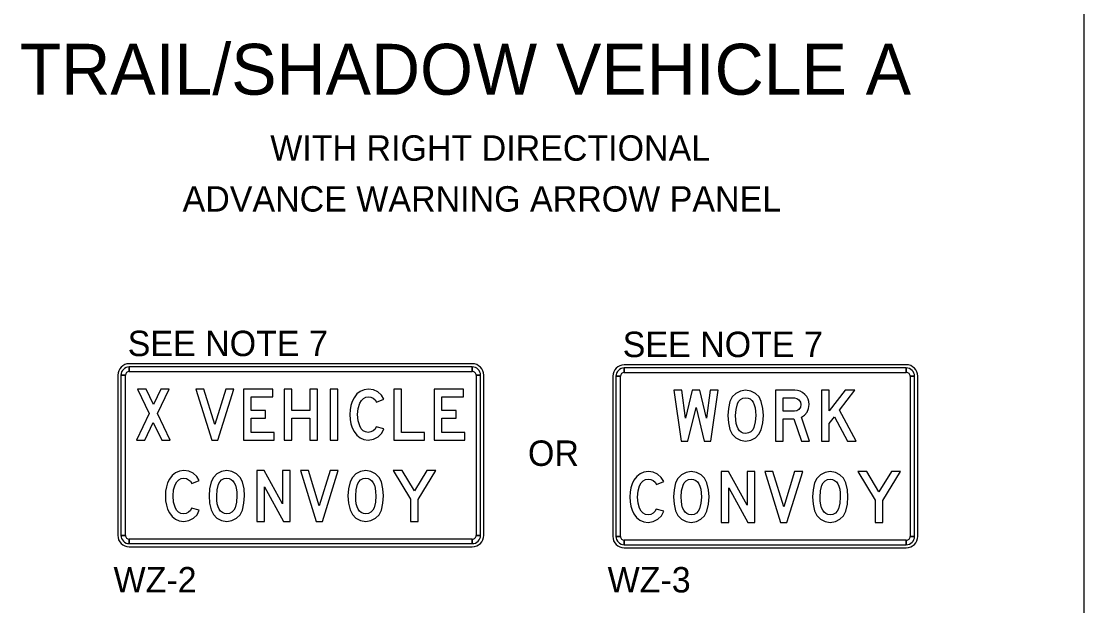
# Model space of a CAD drawing. Extents: x 1374027 to 1374537, y 380415 to 381405.
# Drawn here: x 1374116.23 to 1374141.31, y 381365.09 to 381378.88 of the extents above; entities that cross this region are included whole.
import ezdxf

# ---------------------------------------------------------------- set-up
doc = ezdxf.new("R2010")
doc.units = 0
doc.layers.add('Working Level 1', color=7, linetype='Continuous')

msp = doc.modelspace()

# ---------------------------------------------------------------- linework, layer by layer
at = {"layer": 'Working Level 1'}
for p, q in [((1374141.313, 381402.674), (1374141.313, 381297.674)), ((1374126.877, 381370.796), (1374118.777, 381370.796)), ((1374118.777, 381370.616), (1374118.777, 381370.721)), ((1374126.877, 381370.721), (1374126.877, 381370.616)), ((1374137.124, 381370.772), (1374130.464, 381370.772)), ((1374118.507, 381370.526), (1374118.507, 381366.746)), ((1374118.582, 381370.526), (1374118.687, 381370.526)), ((1374126.967, 381370.526), (1374127.072, 381370.526)), ((1374127.147, 381366.746), (1374127.147, 381370.526)), ((1374130.194, 381370.502), (1374130.194, 381366.722)), ((1374130.269, 381370.502), (1374130.374, 381370.502)), ((1374130.464, 381370.592), (1374130.464, 381370.697)), ((1374137.124, 381370.697), (1374137.124, 381370.592)), ((1374137.214, 381370.502), (1374137.319, 381370.502)), ((1374137.394, 381366.722), (1374137.394, 381370.502)), ((1374118.687, 381366.746), (1374118.582, 381366.746)), ((1374127.072, 381366.746), (1374126.967, 381366.746)), ((1374130.374, 381366.722), (1374130.269, 381366.722)), ((1374137.319, 381366.722), (1374137.214, 381366.722)), ((1374118.777, 381366.551), (1374118.777, 381366.656)), ((1374118.777, 381366.476), (1374126.877, 381366.476)), ((1374126.877, 381366.656), (1374126.877, 381366.551)), ((1374130.464, 381366.527), (1374130.464, 381366.632)), ((1374130.464, 381366.452), (1374137.124, 381366.452)), ((1374137.124, 381366.632), (1374137.124, 381366.527))]:
    msp.add_line(p, q, dxfattribs=at)
for points in [[(1374126.877, 381370.721), (1374118.777, 381370.721), (1374118.777, 381370.616), (1374126.877, 381370.616), (1374126.877, 381370.721)], [(1374118.582, 381370.526), (1374118.582, 381366.746), (1374118.687, 381366.746), (1374118.687, 381370.526), (1374118.582, 381370.526)], [(1374127.072, 381366.746), (1374127.072, 381370.526), (1374126.967, 381370.526), (1374126.967, 381366.746), (1374127.072, 381366.746)], [(1374130.269, 381370.502), (1374130.269, 381366.722), (1374130.374, 381366.722), (1374130.374, 381370.502), (1374130.269, 381370.502)], [(1374137.124, 381370.697), (1374130.464, 381370.697), (1374130.464, 381370.592), (1374137.124, 381370.592), (1374137.124, 381370.697)], [(1374137.319, 381366.722), (1374137.319, 381370.502), (1374137.214, 381370.502), (1374137.214, 381366.722), (1374137.319, 381366.722)], [(1374119.746, 381368.996), (1374119.448, 381369.624), (1374119.722, 381370.196), (1374119.521, 381370.196), (1374119.347, 381369.833), (1374119.174, 381370.196), (1374118.973, 381370.196), (1374119.247, 381369.623), (1374118.946, 381368.996), (1374119.146, 381368.996), (1374119.346, 381369.413), (1374119.546, 381368.996)], [(1374121.245, 381370.196), (1374121.056, 381370.196), (1374120.798, 381369.366), (1374120.541, 381370.196), (1374120.352, 381370.196), (1374120.724, 381368.996), (1374120.873, 381368.996)], [(1374122.202, 381369.177), (1374121.658, 381369.177), (1374121.658, 381369.516), (1374121.998, 381369.516), (1374121.998, 381369.697), (1374121.658, 381369.697), (1374121.658, 381370.014), (1374122.166, 381370.014), (1374122.166, 381370.196), (1374121.477, 381370.196), (1374121.477, 381368.996), (1374122.202, 381368.996)], [(1374123.225, 381368.996), (1374123.225, 381370.196), (1374123.044, 381370.196), (1374123.044, 381369.697), (1374122.614, 381369.697), (1374122.614, 381370.196), (1374122.433, 381370.196), (1374122.433, 381368.996), (1374122.614, 381368.996), (1374122.614, 381369.516), (1374123.044, 381369.516), (1374123.044, 381368.996)], [(1374123.702, 381368.996), (1374123.702, 381370.196), (1374123.521, 381370.196), (1374123.521, 381368.996)], [(1374124.79, 381369.262), (1374124.609, 381369.308), (1374124.582, 381369.255), (1374124.538, 381369.214), (1374124.482, 381369.186), (1374124.419, 381369.177), (1374124.356, 381369.186), (1374124.302, 381369.215), (1374124.256, 381369.263), (1374124.22, 381369.33), (1374124.182, 381369.453), (1374124.17, 381369.596), (1374124.183, 381369.739), (1374124.221, 381369.863), (1374124.259, 381369.929), (1374124.306, 381369.976), (1374124.361, 381370.005), (1374124.425, 381370.014), (1374124.485, 381370.006), (1374124.54, 381369.981), (1374124.585, 381369.942), (1374124.616, 381369.892), (1374124.79, 381369.96), (1374124.731, 381370.056), (1374124.646, 381370.131), (1374124.542, 381370.179), (1374124.428, 381370.196), (1374124.322, 381370.183), (1374124.23, 381370.145), (1374124.151, 381370.083), (1374124.086, 381369.995), (1374124.043, 381369.909), (1374124.013, 381369.814), (1374123.995, 381369.709), (1374123.989, 381369.596), (1374123.995, 381369.483), (1374124.013, 381369.379), (1374124.043, 381369.284), (1374124.085, 381369.198), (1374124.149, 381369.109), (1374124.227, 381369.046), (1374124.318, 381369.008), (1374124.422, 381368.996), (1374124.544, 381369.014), (1374124.654, 381369.07), (1374124.739, 381369.155)], [(1374125.746, 381368.996), (1374125.746, 381369.177), (1374125.202, 381369.177), (1374125.202, 381370.196), (1374125.021, 381370.196), (1374125.021, 381368.996)], [(1374126.702, 381369.177), (1374126.158, 381369.177), (1374126.158, 381369.516), (1374126.498, 381369.516), (1374126.498, 381369.697), (1374126.158, 381369.697), (1374126.158, 381370.014), (1374126.666, 381370.014), (1374126.666, 381370.196), (1374125.977, 381370.196), (1374125.977, 381368.996), (1374126.702, 381368.996)], [(1374132.68, 381370.172), (1374132.497, 381370.172), (1374132.405, 381369.515), (1374132.246, 381370.172), (1374132.071, 381370.172), (1374131.913, 381369.514), (1374131.821, 381370.172), (1374131.637, 381370.172), (1374131.805, 381368.972), (1374131.969, 381368.972), (1374132.159, 381369.762), (1374132.349, 381368.972), (1374132.512, 381368.972)], [(1374133.75, 381369.573), (1374133.738, 381369.744), (1374133.701, 381369.904), (1374133.647, 381370.013), (1374133.561, 381370.098), (1374133.452, 381370.153), (1374133.33, 381370.172), (1374133.208, 381370.153), (1374133.1, 381370.098), (1374133.015, 381370.012), (1374132.961, 381369.903), (1374132.924, 381369.743), (1374132.912, 381369.573), (1374132.924, 381369.403), (1374132.961, 381369.242), (1374133.015, 381369.133), (1374133.1, 381369.047), (1374133.208, 381368.991), (1374133.33, 381368.972), (1374133.452, 381368.991), (1374133.56, 381369.046), (1374133.646, 381369.131), (1374133.7, 381369.24), (1374133.737, 381369.401)], [(1374133.569, 381369.572), (1374133.558, 381369.426), (1374133.526, 381369.291), (1374133.497, 381369.234), (1374133.452, 381369.191), (1374133.396, 381369.163), (1374133.332, 381369.153), (1374133.276, 381369.16), (1374133.227, 381369.18), (1374133.186, 381369.212), (1374133.153, 381369.258), (1374133.127, 381369.317), (1374133.108, 381369.389), (1374133.097, 381369.474), (1374133.093, 381369.572), (1374133.104, 381369.717), (1374133.136, 381369.852), (1374133.164, 381369.909), (1374133.209, 381369.953), (1374133.266, 381369.982), (1374133.332, 381369.991), (1374133.387, 381369.984), (1374133.435, 381369.965), (1374133.476, 381369.932), (1374133.509, 381369.886), (1374133.535, 381369.827), (1374133.554, 381369.756), (1374133.565, 381369.67)], [(1374134.838, 381368.972), (1374134.649, 381369.533), (1374134.723, 381369.585), (1374134.78, 381369.657), (1374134.817, 381369.742), (1374134.83, 381369.835), (1374134.823, 381369.902), (1374134.805, 381369.964), (1374134.773, 381370.021), (1374134.73, 381370.073), (1374134.677, 381370.116), (1374134.62, 381370.147), (1374134.557, 381370.166), (1374134.49, 381370.172), (1374134.037, 381370.172), (1374134.037, 381368.972), (1374134.218, 381368.972), (1374134.218, 381369.493), (1374134.47, 381369.493), (1374134.647, 381368.972)], [(1374134.218, 381369.674), (1374134.218, 381369.991), (1374134.482, 381369.991), (1374134.54, 381369.979), (1374134.589, 381369.944), (1374134.622, 381369.893), (1374134.633, 381369.833), (1374134.622, 381369.771), (1374134.589, 381369.72), (1374134.54, 381369.685), (1374134.482, 381369.674)], [(1374135.938, 381368.972), (1374135.548, 381369.703), (1374135.909, 381370.172), (1374135.68, 381370.172), (1374135.306, 381369.686), (1374135.306, 381370.172), (1374135.125, 381370.172), (1374135.125, 381368.972), (1374135.306, 381368.972), (1374135.306, 381369.389), (1374135.427, 381369.546), (1374135.733, 381368.972)], [(1374120.431, 381367.342), (1374120.249, 381367.388), (1374120.223, 381367.335), (1374120.179, 381367.294), (1374120.122, 381367.266), (1374120.06, 381367.257), (1374119.997, 381367.266), (1374119.943, 381367.295), (1374119.897, 381367.343), (1374119.86, 381367.41), (1374119.823, 381367.533), (1374119.811, 381367.676), (1374119.824, 381367.819), (1374119.862, 381367.943), (1374119.9, 381368.009), (1374119.946, 381368.056), (1374120.001, 381368.085), (1374120.066, 381368.095), (1374120.126, 381368.086), (1374120.18, 381368.061), (1374120.226, 381368.022), (1374120.257, 381367.972), (1374120.431, 381368.04), (1374120.372, 381368.136), (1374120.287, 381368.211), (1374120.183, 381368.259), (1374120.069, 381368.276), (1374119.963, 381368.263), (1374119.871, 381368.225), (1374119.792, 381368.163), (1374119.727, 381368.075), (1374119.684, 381367.989), (1374119.654, 381367.894), (1374119.636, 381367.789), (1374119.63, 381367.676), (1374119.636, 381367.564), (1374119.654, 381367.46), (1374119.683, 381367.364), (1374119.726, 381367.278), (1374119.79, 381367.189), (1374119.867, 381367.126), (1374119.958, 381367.088), (1374120.063, 381367.076), (1374120.185, 381367.094), (1374120.294, 381367.15), (1374120.38, 381367.235)], [(1374121.499, 381367.676), (1374121.487, 381367.848), (1374121.45, 381368.008), (1374121.396, 381368.116), (1374121.31, 381368.202), (1374121.201, 381368.257), (1374121.079, 381368.276), (1374120.957, 381368.257), (1374120.849, 381368.202), (1374120.764, 381368.116), (1374120.71, 381368.007), (1374120.673, 381367.847), (1374120.661, 381367.676), (1374120.673, 381367.506), (1374120.71, 381367.346), (1374120.764, 381367.237), (1374120.849, 381367.151), (1374120.957, 381367.094), (1374121.079, 381367.076), (1374121.201, 381367.094), (1374121.309, 381367.15), (1374121.395, 381367.235), (1374121.449, 381367.344), (1374121.486, 381367.505)], [(1374122.579, 381367.076), (1374122.579, 381368.276), (1374122.398, 381368.276), (1374122.398, 381367.487), (1374121.96, 381368.276), (1374121.786, 381368.276), (1374121.786, 381367.076), (1374121.967, 381367.076), (1374121.967, 381367.89), (1374122.419, 381367.076)], [(1374123.711, 381368.276), (1374123.522, 381368.276), (1374123.264, 381367.447), (1374123.007, 381368.276), (1374122.818, 381368.276), (1374123.189, 381367.076), (1374123.338, 381367.076)], [(1374124.78, 381367.676), (1374124.768, 381367.848), (1374124.731, 381368.008), (1374124.677, 381368.116), (1374124.591, 381368.202), (1374124.483, 381368.257), (1374124.361, 381368.276), (1374124.239, 381368.257), (1374124.131, 381368.202), (1374124.045, 381368.116), (1374123.991, 381368.007), (1374123.954, 381367.847), (1374123.942, 381367.676), (1374123.954, 381367.506), (1374123.991, 381367.346), (1374124.045, 381367.237), (1374124.131, 381367.151), (1374124.239, 381367.094), (1374124.361, 381367.076), (1374124.482, 381367.094), (1374124.591, 381367.15), (1374124.676, 381367.235), (1374124.73, 381367.344), (1374124.767, 381367.505)], [(1374126.017, 381368.276), (1374125.804, 381368.276), (1374125.51, 381367.797), (1374125.222, 381368.276), (1374125.011, 381368.276), (1374125.419, 381367.601), (1374125.419, 381367.076), (1374125.6, 381367.076), (1374125.6, 381367.597)], [(1374131.398, 381367.319), (1374131.216, 381367.365), (1374131.189, 381367.312), (1374131.145, 381367.27), (1374131.089, 381367.243), (1374131.027, 381367.233), (1374130.964, 381367.243), (1374130.909, 381367.272), (1374130.864, 381367.319), (1374130.827, 381367.386), (1374130.79, 381367.509), (1374130.778, 381367.652), (1374130.79, 381367.796), (1374130.828, 381367.919), (1374130.866, 381367.986), (1374130.913, 381368.033), (1374130.968, 381368.062), (1374131.033, 381368.071), (1374131.092, 381368.063), (1374131.147, 381368.038), (1374131.193, 381367.999), (1374131.224, 381367.948), (1374131.398, 381368.017), (1374131.339, 381368.113), (1374131.253, 381368.188), (1374131.149, 381368.236), (1374131.035, 381368.252), (1374130.93, 381368.24), (1374130.838, 381368.202), (1374130.759, 381368.139), (1374130.693, 381368.052), (1374130.651, 381367.965), (1374130.621, 381367.87), (1374130.603, 381367.766), (1374130.597, 381367.653), (1374130.602, 381367.54), (1374130.62, 381367.436), (1374130.65, 381367.341), (1374130.692, 381367.255), (1374130.756, 381367.166), (1374130.834, 381367.103), (1374130.925, 381367.065), (1374131.029, 381367.052), (1374131.151, 381367.071), (1374131.261, 381367.126), (1374131.347, 381367.211)], [(1374132.466, 381367.653), (1374132.453, 381367.824), (1374132.417, 381367.984), (1374132.363, 381368.093), (1374132.277, 381368.178), (1374132.168, 381368.233), (1374132.046, 381368.252), (1374131.924, 381368.233), (1374131.816, 381368.178), (1374131.731, 381368.092), (1374131.677, 381367.983), (1374131.64, 381367.823), (1374131.628, 381367.653), (1374131.64, 381367.483), (1374131.677, 381367.322), (1374131.731, 381367.213), (1374131.816, 381367.127), (1374131.924, 381367.071), (1374132.046, 381367.052), (1374132.168, 381367.071), (1374132.276, 381367.126), (1374132.362, 381367.211), (1374132.416, 381367.32), (1374132.453, 381367.481)], [(1374133.545, 381367.052), (1374133.545, 381368.252), (1374133.364, 381368.252), (1374133.364, 381367.463), (1374132.927, 381368.252), (1374132.753, 381368.252), (1374132.753, 381367.052), (1374132.934, 381367.052), (1374132.934, 381367.866), (1374133.386, 381367.052)], [(1374134.678, 381368.252), (1374134.488, 381368.252), (1374134.231, 381367.423), (1374133.974, 381368.252), (1374133.784, 381368.252), (1374134.156, 381367.052), (1374134.305, 381367.052)], [(1374135.747, 381367.653), (1374135.735, 381367.824), (1374135.698, 381367.984), (1374135.644, 381368.093), (1374135.558, 381368.178), (1374135.449, 381368.233), (1374135.327, 381368.252), (1374135.205, 381368.233), (1374135.097, 381368.178), (1374135.012, 381368.092), (1374134.958, 381367.983), (1374134.921, 381367.823), (1374134.909, 381367.653), (1374134.921, 381367.483), (1374134.958, 381367.322), (1374135.012, 381367.213), (1374135.097, 381367.127), (1374135.205, 381367.071), (1374135.327, 381367.052), (1374135.449, 381367.071), (1374135.557, 381367.126), (1374135.643, 381367.211), (1374135.697, 381367.32), (1374135.734, 381367.481)], [(1374136.984, 381368.252), (1374136.771, 381368.252), (1374136.477, 381367.773), (1374136.189, 381368.252), (1374135.978, 381368.252), (1374136.385, 381367.578), (1374136.385, 381367.052), (1374136.566, 381367.052), (1374136.566, 381367.573)], [(1374121.318, 381367.676), (1374121.307, 381367.53), (1374121.275, 381367.394), (1374121.246, 381367.338), (1374121.201, 381367.294), (1374121.145, 381367.266), (1374121.081, 381367.257), (1374121.025, 381367.263), (1374120.976, 381367.283), (1374120.935, 381367.316), (1374120.902, 381367.362), (1374120.876, 381367.42), (1374120.857, 381367.492), (1374120.846, 381367.577), (1374120.842, 381367.676), (1374120.853, 381367.821), (1374120.885, 381367.956), (1374120.913, 381368.013), (1374120.958, 381368.057), (1374121.015, 381368.085), (1374121.081, 381368.095), (1374121.136, 381368.088), (1374121.184, 381368.068), (1374121.225, 381368.036), (1374121.258, 381367.99), (1374121.284, 381367.931), (1374121.303, 381367.859), (1374121.314, 381367.774)], [(1374124.599, 381367.676), (1374124.588, 381367.53), (1374124.557, 381367.394), (1374124.528, 381367.338), (1374124.483, 381367.294), (1374124.426, 381367.266), (1374124.362, 381367.257), (1374124.306, 381367.263), (1374124.257, 381367.283), (1374124.216, 381367.316), (1374124.183, 381367.362), (1374124.157, 381367.42), (1374124.138, 381367.492), (1374124.127, 381367.577), (1374124.124, 381367.676), (1374124.134, 381367.821), (1374124.166, 381367.956), (1374124.195, 381368.013), (1374124.24, 381368.057), (1374124.297, 381368.085), (1374124.362, 381368.095), (1374124.417, 381368.088), (1374124.465, 381368.068), (1374124.506, 381368.036), (1374124.54, 381367.99), (1374124.565, 381367.931), (1374124.584, 381367.859), (1374124.595, 381367.774)], [(1374132.285, 381367.652), (1374132.274, 381367.506), (1374132.242, 381367.371), (1374132.213, 381367.314), (1374132.168, 381367.271), (1374132.112, 381367.243), (1374132.048, 381367.233), (1374131.991, 381367.24), (1374131.943, 381367.26), (1374131.902, 381367.292), (1374131.869, 381367.338), (1374131.842, 381367.397), (1374131.824, 381367.469), (1374131.813, 381367.554), (1374131.809, 381367.652), (1374131.82, 381367.797), (1374131.852, 381367.932), (1374131.88, 381367.989), (1374131.925, 381368.033), (1374131.982, 381368.062), (1374132.048, 381368.071), (1374132.103, 381368.064), (1374132.151, 381368.045), (1374132.192, 381368.012), (1374132.225, 381367.966), (1374132.251, 381367.907), (1374132.27, 381367.836), (1374132.281, 381367.75)], [(1374135.566, 381367.652), (1374135.555, 381367.506), (1374135.523, 381367.371), (1374135.494, 381367.314), (1374135.449, 381367.271), (1374135.393, 381367.243), (1374135.329, 381367.233), (1374135.273, 381367.24), (1374135.224, 381367.26), (1374135.183, 381367.292), (1374135.15, 381367.338), (1374135.124, 381367.397), (1374135.105, 381367.469), (1374135.094, 381367.554), (1374135.09, 381367.652), (1374135.101, 381367.797), (1374135.133, 381367.932), (1374135.161, 381367.989), (1374135.206, 381368.033), (1374135.263, 381368.062), (1374135.329, 381368.071), (1374135.384, 381368.064), (1374135.432, 381368.045), (1374135.473, 381368.012), (1374135.506, 381367.966), (1374135.532, 381367.907), (1374135.551, 381367.836), (1374135.562, 381367.75)], [(1374118.777, 381366.551), (1374126.877, 381366.551), (1374126.877, 381366.656), (1374118.777, 381366.656), (1374118.777, 381366.551)], [(1374130.464, 381366.527), (1374137.124, 381366.527), (1374137.124, 381366.632), (1374130.464, 381366.632), (1374130.464, 381366.527)]]:
    msp.add_lwpolyline(points, close=True, dxfattribs=at)
for centre, radius, start, end in [((1374118.777, 381370.526), 0.27, 90.0002, 179.9998), ((1374118.777, 381370.526), 0.195, 90.0002, 179.9998), ((1374126.877, 381370.526), 0.27, 0, 90.0002), ((1374126.877, 381370.526), 0.195, 0, 90.0002), ((1374130.464, 381370.502), 0.27, 90.0002, 179.9998), ((1374137.124, 381370.502), 0.27, 0, 90.0002), ((1374118.777, 381370.526), 0.09, 90.0002, 179.9998), ((1374126.877, 381370.526), 0.09, 0, 90.0002), ((1374130.464, 381370.502), 0.195, 90.0002, 179.9998), ((1374130.464, 381370.502), 0.09, 90.0002, 179.9998), ((1374137.124, 381370.502), 0.195, 0, 90.0002), ((1374137.124, 381370.502), 0.09, 0, 90.0002), ((1374118.777, 381366.746), 0.27, 179.9998, 270.0001), ((1374118.777, 381366.746), 0.195, 179.9998, 270.0001), ((1374118.777, 381366.746), 0.09, 179.9998, 270.0001), ((1374126.877, 381366.746), 0.27, 270.0001, 0.0003), ((1374126.877, 381366.746), 0.195, 270.0001, 0.0003), ((1374126.877, 381366.746), 0.09, 270.0001, 0.0003), ((1374130.464, 381366.722), 0.27, 179.9998, 270.0001), ((1374130.464, 381366.722), 0.195, 179.9998, 270.0001), ((1374130.464, 381366.722), 0.09, 179.9998, 270.0001), ((1374137.124, 381366.722), 0.27, 270.0001, 0.0003), ((1374137.124, 381366.722), 0.195, 270.0001, 0.0003), ((1374137.124, 381366.722), 0.09, 270.0001, 0.0003)]:
    msp.add_arc(centre, radius, start, end, dxfattribs=at)

# ---------------------------------------------------------------- texts
for s, height, p in [('TRAIL/SHADOW VEHICLE A', 1.2, (1374116.192, 381377.145)), ('WITH RIGHT DIRECTIONAL', 0.6, (1374122.107, 381375.586)), ('ADVANCE WARNING ARROW PANEL', 0.6, (1374120.037, 381374.386)), ('SEE NOTE 7 ', 0.6, (1374118.741, 381370.976)), ('SEE NOTE 7 ', 0.6, (1374130.428, 381370.953))]:
    msp.add_text(s, height=height, dxfattribs=at).set_placement(p)
for s, p in [('OR', (1374128.191, 381368.386)), ('WZ-2', (1374118.407, 381365.4)), ('WZ-3', (1374130.072, 381365.4))]:
    msp.add_text(s, height=0.6, rotation=0, dxfattribs=at).set_placement(p)

doc.saveas('drawing.dxf')
